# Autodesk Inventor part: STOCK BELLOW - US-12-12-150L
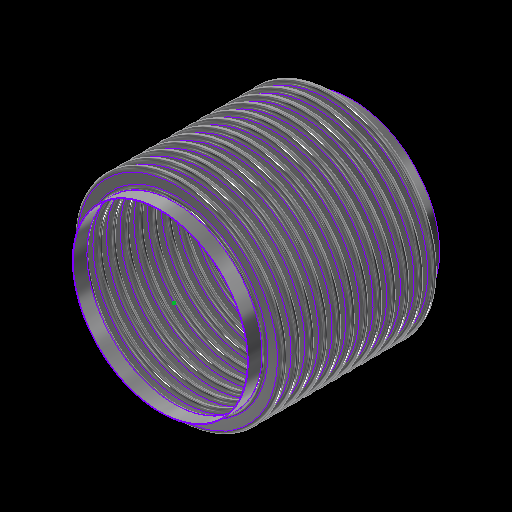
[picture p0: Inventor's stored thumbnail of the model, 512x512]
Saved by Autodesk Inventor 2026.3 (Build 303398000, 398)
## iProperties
Category: 16 GA (0.060 THICK)
RuleStatus: InUse
Created: 2024-01
Part Number: STOCK BELLOW - US-12-12-150L
Project: =STOCK BELLOWS: <Stock Number><SFILL>
Material: ASTM A240-304
Description: =STOCK BELLOWS: <Stock Number>, <SID_> I.D., <SOD_> O.D., <SPLY_> PLY, <Category>, <SNET_CONS> CONS.<PITCH_><STANGENT_> TANGENT<SFILL>
Document SubType Name: Sheet Metal
Designer: GS
Stock Number: U.S-12-12-150L
Surface Area: 21227.4 cm^2
Volume: 1610.4 cm^3
Sheet Metal Rule: Default
Appearance: STAINLESS STEEL
Mass: 12975.5 g
Density: 8.05729 g/cm^3
THK: 0.036
ID: 3.500
OD: 4.250
CONS_: 2
PITCH: 0.500
TANGENT: 0.500
BELLOWS_UPSET: 0.000
d79: 1.000
d82: 1.000
d83: 26.000
d84: 24.000
d174: 8
d214: 8
STHK_: 0.060
SID_: 12.750
SOD_: 15.250
SPITCH_: 1.000
STANGENT__: 1.000
SBELLOWS_UPSET_: 0.000
SDIFF_TAN: 1.000
d252: 2
d275: 2
d287: 0.050
d289: 0.500
d290: 0.000
SOD_NECK: 12 7/8
PLY: 1
PSET: 4.178
PBAR: 1.035
COUNTER: 1.500
NET_TUBE: 3.071
CONS: 2
S_CONS: 0
NET_CONS: 2
ID_M: 88.90 mm
OD_M: 107.95 mm
THK_M: 0.91 mm
ID_U: 3.500 in
OD_U: 4.250 in
THK_U: 0.036 in
TANGENT2: 0.500
TAN_TO_TAN: 1.000 in
d80: 2.571
d81: 10
SID: 2.375
SCONS_: 12
SPITCH: 0.250
STANGENT_: 1.000
SBELLOWS_UPSET: 0.000
SNET_CONS: 12
SS_CONS: 0
SCONS: 8
d190: 8
d191: 1
d192: 1
d193: 8
d194: 0
SIZE: 12.00
PRESSURE: 150
d230: 8
STANGENT: 4.000
SPLY_: 1
d233: 8
d234: 0
d263: 2
d265: 1
d268: 2
d269: 0
d286: 2
d288: 1
d291: 2
d292: 0
SREROLL: 0.750
BLETP: 1.000 ul
PRES_Copy: 85
MATTABLE: 20 GA (0.036 THICK)
PART_NUMBER: U.S-12-12-150L
PITCH_: =, <SPITCH_> PITCH,
CFILL: .
SFILL: .
MESH: ,
COMP: 2.31
EXT: 1.16
LAT: 0.66
ANG: 573
ASR: 2354
LSR: 4326
ANSR: 906
PRES: 150
COMPM: 23.1
EXTM: 11.55
LATM: 6.60
ASRM: 412.256
PRESM: 10.342
LSRM: 757.612
ANSRM: 158.668
TEMPMIN: 20
TEMPMAX: 800
TEMPMINM: -7
TEMPMAXM: 427
WEIGHTM: 12.975
WEIGHT: 28.606
Author: GS
Keywords: 20 GA (0.036 THICK)
Comments: =STOCK BELLOW - <STOCK NUMBER>
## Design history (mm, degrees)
sketch "Sketch2"
  geometry: L1 (0, -177.245)-(0, 562.856) reference; L2 (45.364, 0)-(44.45, 0); L3 (48.082, -2.718)-(50.343, -2.718); L4 (48.082, -3.632)-(50.343, -3.632); L5 (50.343, -9.982)-(48.082, -9.982); L6 (50.343, -9.068)-(48.082, -9.068); L7 (45.364, -12.7)-(44.45, -12.7); L8 (48.082, 0)-(48.082, -12.7); L9 (50.343, -6.35)-(53.975, -6.35); L10 (44.45, 0)-(44.45, -12.7); L11 (20.376, 102.841)-(20.376, 101.926); L12 (58.262, 457.127)-(58.262, 349.177); L13 (58.262, 444.427)-(58.262, 336.477); L14 (93.133, -58.817)-(93.133, -71.517); L15 (118.746, -66.401)-(118.746, -66.401); L16 (50.343, -9.068)-(50.343, -9.982); L17 (48.082, -9.068)-(48.082, -9.982); L18 (48.082, -9.525)-(50.343, -9.525); L19 (53.975, 0)-(53.975, -12.7); L20 (-50.343, -9.068)-(-50.343, -9.982); L21 (-50.343, -2.718)-(-48.082, -2.718); L22 (-50.343, -3.632)-(-48.082, -3.632); L23 (-48.082, -9.068)-(-50.343, -9.068); L24 (-50.343, -9.525)-(-48.082, -9.525); L25 (-48.082, -9.982)-(-50.343, -9.982); L26 (-48.082, -9.068)-(-48.082, -9.982); L27 (-44.45, 0.653)-(-44.45, -12.047); L28 (-48.082, -6.35)-(-44.45, -6.35); L29 (-50.343, 0.653)-(-50.343, -12.7); L30 (-53.061, 0)-(-53.975, 0); L31 (-53.975, 0)-(-53.975, -12.7); L32 (-53.061, -12.7)-(-53.975, -12.7); A1 r 2.718 centre (48.082, 0) between (45.364, 0) and (48.082, -2.718); A2 r 3.632 centre (48.082, 0) between (44.45, 0) and (48.082, -3.632); A3 r 3.632 centre (50.343, -6.35) between (50.343, -9.982) and (50.343, -2.718); A4 r 2.718 centre (50.343, -6.35) between (50.343, -9.068) and (50.343, -3.632); A5 r 2.718 centre (48.082, -12.7) between (48.082, -9.982) and (45.364, -12.7); A6 r 3.632 centre (48.082, -12.7) between (48.082, -9.068) and (44.45, -12.7); A7 r 3.175 centre (50.343, -6.35) between (50.343, -9.525) and (53.518, -6.35); A8 r 3.175 centre (48.082, -12.7) between (48.082, -9.525) and (44.907, -12.7); A9 r 2.718 centre (-50.343, -12.7) between (-50.343, -9.982) and (-53.061, -12.7); A10 r 2.718 centre (-48.082, -6.35) between (-48.082, -9.068) and (-48.082, -3.632); A11 r 3.175 centre (-48.082, -6.35) between (-48.082, -9.525) and (-44.907, -6.35); A12 r 3.632 centre (-48.082, -6.35) between (-48.082, -9.982) and (-48.082, -2.718); A13 r 3.175 centre (-50.343, -12.7) between (-50.343, -9.525) and (-53.518, -12.7); A14 r 3.632 centre (-50.343, -12.7) between (-50.343, -9.068) and (-53.975, -12.7); A15 r 2.718 centre (-50.343, 0) between (-53.061, 0) and (-50.343, -2.718); A16 r 3.632 centre (-50.343, 0) between (-53.975, 0) and (-50.343, -3.632); 10 further points
  constraints: 62 end point, 38 point on circle, 20 tangent, 16 centre point, 12 parallel, 9 midpoint, 7 vertical, 6 coincident, 6 concentric, 6 point on line, 4 equal radius, 4 perpendicular, 3 horizontal, 1 collinear, 1 horizontal alignment, 10 other
  dimensions: "THK" = 0.9144 distance of L11.start L11.end; "ID" = 88.9 distance of L11.end point (20.376, 13.026); "OD" = 107.95 distance of L12.start L12.end; "PITCH" = 12.7 distance of L12.start L13.start; "TANGENT" = 12.7 distance of L14.start L14.end; "BELLOWS_UPSET" = 0 distance of L15.start L15.end; "d43" = 88.9 diameter of L10 L1 (= ID); "d44" = 107.95 diameter of L9.end L1 (= OD); "d45" = 0.9144 distance between parallel lines of L5 L6 (computed from THK, PLY); "d46" = 3.6322 radius of A3 (computed from PITCH, THK, PLY); "UPSET_PITCH" = 12.7 distance of L2.end L7.end (derived); "SIDEWALL_ANGLE" = 360 deg dimension on L3 L9 (derived); "CON_GAP" = 5.4356 distance of point (48.082, -9.068) point (48.082, -3.632) (derived); "TAN1" = 4.98728 dimension on A8 (derived); "TAN2" = 4.98728 dimension on A7 (derived); "LEG1" = 2.2606 distance of L18.start L18.end (derived); "d278" = 0.9144 distance between parallel lines of L25 L23 (derived); "d279" = 3.6322 radius of A12 (derived); "d280" = 12.7 distance of L30.end L31.end (derived); "d281" = 360 deg dimension on L21 L28 (derived); "d282" = 5.4356 distance of point (-50.343, -9.068) point (-50.343, -3.632) (derived); "d283" = 4.98728 dimension on A13 (derived); "d284" = 4.98728 dimension on A11 (derived); "d285" = 2.2606 distance of L24.start L24.end (derived); "d293" = 88.9 diameter of L27 L1 (derived); "d294" = 107.95 diameter of L31 L1 (derived)
  node "Sketch Rectangular Pattern1" dims "d31" = 25.4, "ID" = 88.9
  node "Sketch Rectangular Pattern2" dims "d39" = 25.4, "PITCH" = 12.7
revolve "CONS" stored, may be unused: angle "d48" = 90 deg
node "BELLOW MIDPLANE"
pattern_linear "Rectangular Pattern2" dims "d52" = 12.7 (= UPSET_PITCH)
sketch "Sketch5"
  geometry: C1 r 45.364 at (0, 0) reference; C2 r 44.45 at (0, 0) reference
extrude "TANGENT" new body sketch "Sketch5" distance "d53" = 12.7 (= TANGENT); taper "d54" = 0 deg
revolve "SAMETAN" stored, may be unused: angle "d65" = 90 deg
revolve "DIFFTAN" stored, may be unused: angle "d70" = 90 deg
sketch "Sketch9"
  geometry: L1 (53.319, 0)-(-53.319, 0) reference; L2 (0, -17.78)-(0, 17.78) reference; L3 (38.085, 0)-(-38.085, 0); L4 (38.085, -11.906)-(38.085, 11.906); L5 (25.385, -11.906)-(25.385, 11.906); L6 (13.15, 11.906)-(13.15, -11.906); L7 (-25.385, -11.906)-(-25.385, 11.906); L8 (-38.085, -11.906)-(-38.085, 11.906); L9 (37.291, -11.906)-(37.291, 11.906); L10 (38.085, -11.906)-(37.291, -11.906); L11 (38.085, 11.906)-(37.291, 11.906); L12 (13.546, 11.906)-(12.753, 11.906); L13 (12.753, 11.906)-(12.753, -11.906); L14 (12.753, -11.906)-(13.546, -11.906); L15 (13.546, -11.906)-(13.546, 11.906); L16 (-13.546, 11.906)-(-13.546, -11.906); L17 (-13.15, 11.906)-(-13.15, -11.906); L18 (-13.546, -11.906)-(-12.753, -11.906); L19 (-12.753, -11.906)-(-12.753, 11.906); L20 (-12.753, 11.906)-(-13.546, 11.906); L21 (-38.085, -11.906)-(-37.291, -11.906); L22 (-37.291, -11.906)-(-37.291, 11.906); L23 (-37.291, 11.906)-(-38.085, 11.906); L24 (-38.085, 11.906)-(-38.085, -11.906); L25 (38.085, -0.397)-(-38.085, -0.397); L26 (-38.085, -0.397)-(-38.085, 0.397); L27 (-38.085, 0.397)-(38.085, 0.397); L28 (38.085, 0.397)-(38.085, -0.397); L29 (-38.085, 11.906)-(38.085, 11.906); L30 (38.085, 11.906)-(38.085, 12.7); L31 (38.085, 12.7)-(-38.085, 12.7); L32 (-38.085, 12.7)-(-38.085, 11.906); L33 (38.085, -11.906)-(-38.085, -11.906); L34 (-38.085, -11.906)-(-38.085, -12.7); L35 (-38.085, -12.7)-(38.085, -12.7); L36 (38.085, -12.7)-(38.085, -11.906); 30 further points
  constraints: 68 end point, 13 midpoint, 13 parallel, 8 horizontal, 7 perpendicular, 6 equal length, 3 point on line, 2 vertical, 14 other
  dimensions: "d115" = 23.8125 distance of L4.start L4.end (derived); "d116" = 12.7 distance between parallel lines of L4 L5 (derived); "d117" = 12.23516 distance between parallel lines of L5 L6 (derived); "d125" = 38.53427 distance between parallel lines of L7 L6 (derived); "d127" = 12.7 distance between parallel lines of L8 L7 (derived); "d128" = 24.93516 distance between parallel lines of L6 L4 (derived); "d130" = 76.16943 distance between parallel lines of L8 L4 (derived); "RULER_THK" = 0.79375 distance between parallel lines of L4 L9; "d135" = 0.79375 distance of L13.end L14.end (derived); "d138" = 26.29911 distance of L13.end L16.end (derived); "d143" = 0.79375 distance of L22.end L8.end (derived); "d144" = 0.79375 distance between parallel lines of L27 L25 (derived)
extrude "RULER" join sketch "Sketch9" distance "d149" = 0.79375 (derived); taper "d150" = 0 deg
extrude "BARS" join sketch "Sketch9" distance "d151" = 0.79375 (derived); taper "d152" = 0 deg
pattern_linear "Rectangular Pattern4" dims "d155" = 26.29911 (derived)
sketch "Sketch13"
  geometry: L1 (93.149, -52.467)-(93.149, -77.867); L2 (163.449, 0)-(161.925, 0); L3 (163.449, -25.4)-(161.925, -25.4); L4 (186.563, -19.812)-(169.037, -19.812); L5 (186.563, -18.288)-(169.037, -18.288); L6 (186.563, -12.7)-(193.675, -12.7); L7 (169.037, -5.588)-(186.563, -5.588); L8 (169.037, 0)-(169.037, -25.4); L9 (161.925, 0)-(161.925, -25.4); L10 (58.254, -109.081)-(58.254, -496.431); L11 (58.254, -134.481)-(58.254, -521.831); L12 (58.254, -185.281)-(58.254, -572.631); L13 (58.254, -210.681)-(58.254, -598.031); L14 (58.254, -236.081)-(58.254, -623.431); L15 (58.254, -261.481)-(58.254, -648.831); L16 (58.254, -286.881)-(58.254, -674.231); L17 (58.254, -159.881)-(58.254, -547.231); L18 (20.376, 103.45)-(20.376, 101.926); L19 (169.037, -7.112)-(186.563, -7.112); L20 (0, -829.767)-(0, 258.986) reference; L21 (-38.735, 0)-(232.41, 0) reference; A1 r 5.588 centre (169.037, 0) between (163.449, 0) and (169.037, -5.588); A2 r 5.588 centre (169.037, -25.4) between (169.037, -19.812) and (163.449, -25.4); A3 r 7.112 centre (169.037, -25.4) between (169.037, -18.288) and (161.925, -25.4); A4 r 5.588 centre (186.563, -12.7) between (186.563, -18.288) and (186.563, -7.112); A5 r 7.112 centre (186.563, -12.7) between (186.563, -19.812) and (186.563, -5.588); A6 r 7.112 centre (169.037, 0) between (161.925, 0) and (169.037, -7.112); 6 further points; 1 other entity
  constraints: 38 end point, 15 point on circle, 9 tangent, 6 centre point, 6 parallel, 5 vertical alignment, 4 point on line, 4 vertical, 3 coincident, 3 concentric, 2 collinear, 2 equal radius, 1 horizontal, 1 perpendicular, 23 other
  dimensions: "SBELLOWS_UPSET_" = 0 distance of point (118.762, -66.401) point (118.762, -66.401); "STOTAL_THK_BELLOW__" = 1.524 distance between parallel lines of L4 L5 (derived); "d224" = 7.112 radius of A5 (derived); "d225" = 25.4 distance of L2.end L3.end (derived); "SSIDEWALL_ANGLE_" = 360 deg dimension on L7 L6 (derived); "SSCON_GAP_" = 11.176 distance of point (169.037, -18.288) point (169.037, -7.112) (derived); "d235" = 323.85 diameter of L9 L20 (derived); "d236" = 387.35 diameter of L6.end L20 (derived)
  node "Sketch Rectangular Pattern4" dims "d228" = 25.4
  node "Sketch Rectangular Pattern5" dims "d229" = 25.4
revolve "SBELLOW" stored, may be unused: angle "d197" = 90 deg
pattern_linear "Rectangular Pattern5" dims "d204" = 25.4 (derived)
revolve "STANGENT" stored, may be unused: angle "d240" = 90 deg
revolve "SSAMETAN" stored, may be unused: angle "d241" = 90 deg
revolve "SDIFFTAN" stored, may be unused: angle "d246" = 90 deg
revolve "INVCON" stored, may be unused: angle "d295" = 90 deg
pattern_linear "Rectangular Pattern6" dims "d298" = 12.7 (derived)
revolve "INVTANGENT" stored, may be unused: angle "d302" = 90 deg
revolve "INVSAMETAN" stored, may be unused: angle "d307" = 90 deg
revolve "INVDIFFTAN" stored, may be unused: angle "d312" = 90 deg
sketch "ID BELLOW MOUNT CALC"
  geometry: L1 (44.45, 0)-(38.1, 0); L2 (38.1, 0)-(38.1, 12.7); L3 (38.1, 12.7)-(44.45, 12.7); L4 (44.45, 12.7)-(44.45, 0); L5 (36.513, 12.7)-(35.598, 12.7); L6 (35.598, 12.7)-(35.598, 0); L7 (35.598, 0)-(36.513, 0); L8 (36.513, 0)-(36.513, 12.7); L9 (0, -2.54)-(0, 15.24) reference; L10 (-8.89, 0)-(53.34, 0) reference; 1 further point
  constraints: 16 end point, 5 parallel, 2 collinear, 2 horizontal, 2 perpendicular
  dimensions: "d314" = 12.7 distance of L5.end L6.end (derived); "d315" = 0.9144 distance of L5.start L5.end (derived); "IG" = 1.5875 distance between parallel lines of L2 L8; "PIPE_OD" = 88.9 diameter of L4 L9; "PIPE_WALL" = 6.35 distance of L2.end L3.end; "ID_MT_BELLOW" = 71.1962 diameter of L6 L9 (derived)
revolve "CFILL" stored, may be unused: angle "d320" = 90 deg
pattern_linear "Rectangular Pattern7" dims "d323" = 12.7 (derived)
revolve "SFILL" stored, may be unused: angle "d324" = 90 deg
pattern_linear "Rectangular Pattern8" dims "d327" = 25.4 (derived)
node "STOCK BELLOW MIDPLANE"
node "BELLOW"
sketch "Sketch6"
  geometry: L1 (-12.7, 45.364)-(0, 45.364); L2 (0, 45.364)-(0, 44.45); L3 (0, 44.45)-(-12.7, 44.45); L4 (-12.7, 44.45)-(-12.7, 45.364); L5 (10.16, 0)-(-60.96, 0) reference; L6 (-38.1, -89.422)-(-38.1, 153.44) reference; 1 further point
  constraints: 8 end point, 2 parallel, 1 horizontal, 1 perpendicular
  dimensions: "d61" = 12.7 distance of L2.end L3.end (derived); "d62" = 0.9144 distance of L1.end L2.end (derived); "d63" = 88.9 diameter of L3 L5 (derived); "d64" = 25.4 distance between parallel lines of L4 L6 (derived)
sketch "Sketch12"
  geometry: 1 further point
sketch "Sketch14"
  geometry: L1 (-25.4, 163.449)-(0, 163.449); L2 (0, 163.449)-(0, 161.925); L3 (0, 161.925)-(-25.4, 161.925); L4 (-25.4, 161.925)-(-25.4, 163.449); L5 (5.08, 0)-(-30.48, 0) reference; L6 (0, -32.69)-(0, 196.139) reference; 1 further point
  constraints: 8 end point, 2 parallel, 1 collinear, 1 horizontal, 1 perpendicular
  dimensions: "d237" = 1.524 distance of L3.end L1.start (derived); "d238" = 323.85 diameter of L3 L5 (derived); "d239" = 25.4 distance of L1.start L1.end (derived); "SOD_NECK" = 326.898 diameter of L1 L5 (derived)
sketch "Sketch15"
  geometry: L1 (-32.69, 0)-(196.139, 0) reference; L2 (161.925, -304.8)-(163.449, -304.8); L3 (163.449, -304.8)-(163.449, -330.2); L4 (163.449, -330.2)-(161.925, -330.2); L5 (161.925, -330.2)-(161.925, -304.8); L6 (0, -398.78)-(0, 81.28) reference; 1 further point
  constraints: 8 end point, 2 parallel, 1 horizontal, 1 perpendicular
  dimensions: "d205" = 25.4 distance of L4.end L2.start (derived); "d206" = 1.524 distance of L3.end L4.end (derived); "d207" = 323.85 diameter of L5 L6 (derived); "d208" = 304.8 distance between parallel lines of L1 L2 (derived)
node "TANGENT_"
node "SAME_TAN"
sketch "Sketch8"
  geometry: L1 (45.364, -25.4)-(44.45, -25.4); L2 (44.45, -25.4)-(44.45, -38.1); L3 (44.45, -38.1)-(45.364, -38.1); L4 (45.364, -38.1)-(45.364, -25.4); L5 (0, -48.26)-(0, 22.86) reference; L6 (-89.422, 0)-(153.44, 0) reference; 1 further point
  constraints: 8 end point, 2 parallel, 1 horizontal, 1 perpendicular
  dimensions: "d66" = 88.9 diameter of L2 L5 (derived); "TOTAL_THK_BELLOW" = 0.9144 distance of L2.end L3.end (derived); "d68" = 25.4 distance between parallel lines of L1 L6 (derived); "d69" = 12.7 distance of L1.end L2.end (derived)
node "DIFF_TAN"
node "Sketch Rectangular Pattern3" dims "d138" = 26.29911 (derived), "d141" = 25.4
node "SBELLOW_"
node "STANGENT_"
node "SSAME_TAN"
sketch "Sketch16"
  geometry: L1 (163.449, -304.8)-(161.925, -304.8); L2 (161.925, -304.8)-(161.925, -330.2); L3 (161.925, -330.2)-(163.449, -330.2); L4 (163.449, -330.2)-(163.449, -304.8); L5 (0, -398.78)-(0, 81.28) reference; L6 (-32.69, 0)-(196.139, 0) reference; 1 further point
  constraints: 8 end point, 2 parallel, 1 horizontal, 1 perpendicular
  dimensions: "SDIFF_TAN" = 25.4 distance of L3.end L1.start; "d243" = 1.524 distance of L2.end L3.end (derived); "d244" = 304.8 distance between parallel lines of L1 L6 (derived); "d245" = 323.85 diameter of L2 L5 (derived)
node "SDIFF_TAN"
body "Solid15"
sketch "Sketch17"
  geometry: L1 (53.975, 12.7)-(53.061, 12.7); L2 (53.061, 12.7)-(53.061, 0); L3 (53.061, 0)-(53.975, 0); L4 (53.975, 0)-(53.975, 12.7); L5 (0, -2.54)-(0, 15.24) reference; L6 (-10.795, 0)-(64.77, 0) reference; 2 further points
  constraints: 8 end point, 2 parallel, 1 horizontal, 1 midpoint, 1 perpendicular, 1 point on line
  dimensions: "INVTANGENT" = 12.7 distance of L3.end L1.start (derived); "d300" = 0.9144 distance of L1.start L1.end (derived); "d301" = 107.95 diameter of L4 L5 (derived)
body "Solid16"
sketch "Sketch18"
  geometry: L1 (53.975, -25.4)-(53.061, -25.4); L2 (53.061, -25.4)-(53.061, -38.1); L3 (53.061, -38.1)-(53.975, -38.1); L4 (53.975, -38.1)-(53.975, -25.4); L5 (-10.795, 0)-(64.77, 0) reference; L6 (0, -48.26)-(0, 22.86) reference; 1 further point
  constraints: 8 end point, 2 parallel, 1 horizontal, 1 perpendicular
  dimensions: "d303" = 25.4 distance between parallel lines of L1 L5 (derived); "d304" = 12.7 distance of L3.end L1.start (derived); "d305" = 0.9144 distance of L2.end L3.end (derived); "d306" = 107.95 diameter of L4 L6 (derived)
body "Solid17"
sketch "Sketch19"
  geometry: L1 (53.975, -25.4)-(53.061, -25.4); L2 (53.061, -25.4)-(53.061, -38.1); L3 (53.061, -38.1)-(53.975, -38.1); L4 (53.975, -38.1)-(53.975, -25.4); L5 (0, -48.26)-(0, 22.86) reference; L6 (-10.795, 0)-(64.77, 0) reference; 1 further point
  constraints: 8 end point, 2 parallel, 1 horizontal, 1 perpendicular
  dimensions: "d308" = 12.7 distance of L1.end L2.end (derived); "d309" = 107.95 diameter of L4 L5 (derived); "d310" = 0.9144 distance of L2.end L3.end (derived); "d311" = 25.4 distance between parallel lines of L1 L6 (derived)
body "Solid18"
body "Solid19"
body "Solid20"
other parameters: "BMPL" = -152.4, "PSET" = 106.1212 (computed from OD, THK, PLY) [user parameter], "PBAR" = 26.29911 (= 0.570796 x PITCH + OD - ID) [user parameter; used in 1 equation term], "COUNTER" = 15 [user parameter], "NET_TUBE" = 77.99823 (computed from CONS_, PBAR, TANGENT) [user parameter], "S_CONS" = 0 [user parameter; used in 1 equation term], "ID_M" = 88.9 (= ID) [user parameter], "OD_M" = 107.95 (= OD) [user parameter], "THK_M" = 0.9144 (= THK) [user parameter], "ID_U" = 88.9 (= ID) [user parameter], "OD_U" = 107.95 (= OD) [user parameter], "THK_U" = 0.9144 (= THK) [user parameter], "D_UNITS" = 0 [user parameter], "TANGENT2" = 12.7 [user parameter], "TAN_TO_TAN" = 25.4 [user parameter], "OD_NECK" = 90.7288 [user parameter], "d79" = 25.4, "d80" = 65.29823 [user parameter], "d82" = 25.4, "d83" = 660.4, "d84" = 609.6, "sa_0" = 4, "FRAME_THK" = 0.79375 [user parameter], "CON_FLAT" = 12.23516 [user parameter], "SID" = 60.325 [user parameter], "SPITCH" = 6.35 [user parameter], "STANGENT_" = 25.4 [user parameter], "SBELLOWS_UPSET" = 0 [user parameter], "SS_CONS" = 0 [user parameter], "STAN_TO_TAN_" = 304.8 [user parameter], "d100" = 1.524 [user parameter], "d191" = 25.4 [user parameter], "d194" = 0 [user parameter], "STANGENT" = 101.6 [user parameter], "d234" = 0 [user parameter], "SUPSET_PITCH_" = 25.4 [user parameter], "d269" = 0 [user parameter], "d287" = 1.27, "d289" = 12.7, "d290" = 0, "d292" = 0 [user parameter], "Thickness" = 3.048 (derived), "KFactor" = 4.4, "BendRadius" = 3.048 (derived), "BendReliefWidth" = 3.048 (derived), "BendReliefDepth" = 1.524 (derived), "CornerReliefSize" = 12.192 (derived), "SeamGap" = 0.00508, "MinimumRemnant" = 6.096 (derived), "TransitionRadius" = 3.048 (derived), "JacobiRadiusSize" = 3.048 (derived), "GapSize" = 3.048 (derived), "SREROLL" = 19.05 [user parameter], "CUR_STK_PITCH" = 25.4 [user parameter], "d328" = -152.4 (derived), "ASR" = 23540 [user parameter], "LSR" = 43260 [user parameter], "BLETP" = 1 [user parameter], "ASRM" = 4122.5602 [user parameter], "PRESM" = 103.41975 [user parameter], "LSRM" = 7576.1238 [user parameter], "ANSRM" = 1586.6778 [user parameter], "TEMPMIN" = 2664.83333 [user parameter], "TEMPMAX" = 6998.16667 [user parameter], "TEMPMINM" = 2664.83333 [user parameter], "TEMPMAXM" = 6998.16667 [user parameter], "WEIGHT" = 129.75486 [user parameter], "WEIGHTM" = 0.12975 [user parameter]
